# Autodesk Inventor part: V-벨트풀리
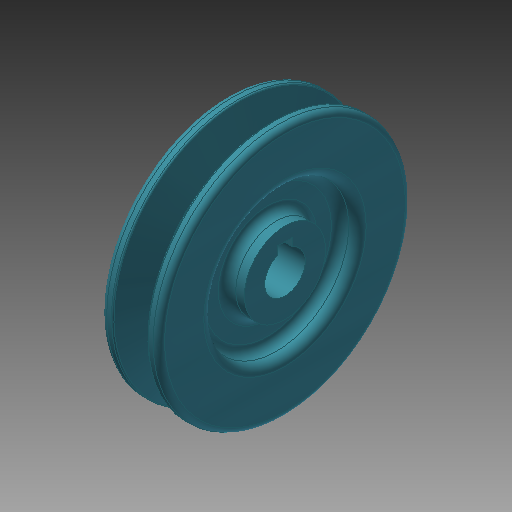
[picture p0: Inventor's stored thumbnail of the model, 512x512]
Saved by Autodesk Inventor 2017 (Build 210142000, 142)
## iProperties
Created: 2019-09
Part Number: V-벨트풀리
Material: 알루미늄 6061
Document SubType Name: Modeling
Designer: mduedu
Density: 2.71 g/cm^3
Appearance: 커뎃 파란색
Mass: 202.902 g
Surface Area: 230.066 cm^2
Volume: 74.8717 cm^3
Author: mduedu
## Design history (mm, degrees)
sketch "스케치1"
  geometry: L1 (-10, 0)-(10, 0); L2 (10, 0)-(10, 43.5); L3 (10, 43.5)-(-10, 43.5); L4 (-10, 43.5)-(-10, 0); L5 (0, 0)-(0, 43.5); L6 (-5.976, 43.5)-(-2.154, 31); L7 (-2.154, 31)-(2.154, 31); L8 (2.154, 31)-(5.976, 43.5); L9 (-10, 39)-(10, 39); 3 further points
  constraints: 18 end point, 8 point on line, 3 perpendicular, 2 midpoint, 2 parallel, 1 coincident, 1 horizontal, 1 other
  dimensions: "d0" = 87 diameter of L3 L1; "d3" = 12.5 distance between parallel lines of L7 L3; "d4" = 34 deg angle of L8 L6; "d5" = 20 distance between parallel lines of L2 L4; "d6" = 8 distance between parallel lines of L9 L7; "d7" = 9.2 distance of point (4.6, 39) point (-4.6, 39)
revolve "회전1" sketch "스케치1" stored, may be unused: angle "d8" = 90 deg
sketch "스케치2"
  geometry: C1 r 14 at (0, 0); C2 r 25 at (0, 0); 1 further point
  constraints: 2 centre point, 2 coincident
  dimensions: "d9" = 28 diameter of C1; "d10" = 50 diameter of C2
extrude "돌출1" cut sketch "스케치2" distance "d11" = 6; taper "d12" = 0 deg
fillet "모깎기1" dims "d13" = 3
fillet "모깎기2" dims "d14" = 3
fillet "모깎기3" dims "d15" = 0.5, "d16" = 1, "d17" = 2
sketch "스케치3"
  geometry: L1 (-2.5, 6.538)-(2.5, 6.538); L2 (2.5, 6.538)-(2.5, 9.3); L3 (2.5, 9.3)-(-2.5, 9.3); L4 (-2.5, 9.3)-(-2.5, 6.538); A1 r 7 centre (0, 0) between (-2.5, 6.538) and (2.5, 6.538); 1 further point
  constraints: 8 end point, 2 parallel, 2 point on circle, 1 centre point, 1 coincident, 1 horizontal, 1 perpendicular
  dimensions: "d18" = 14 diameter of A1; "d20" = 5 distance of L2.end L3.end; "d21" = 16.3 dimension on A1 L3
extrude "돌출2" cut sketch "스케치3" stored distance "d22" = 6; taper "d23" = 0 deg
node "솔리드1"
mirror "대칭1"
